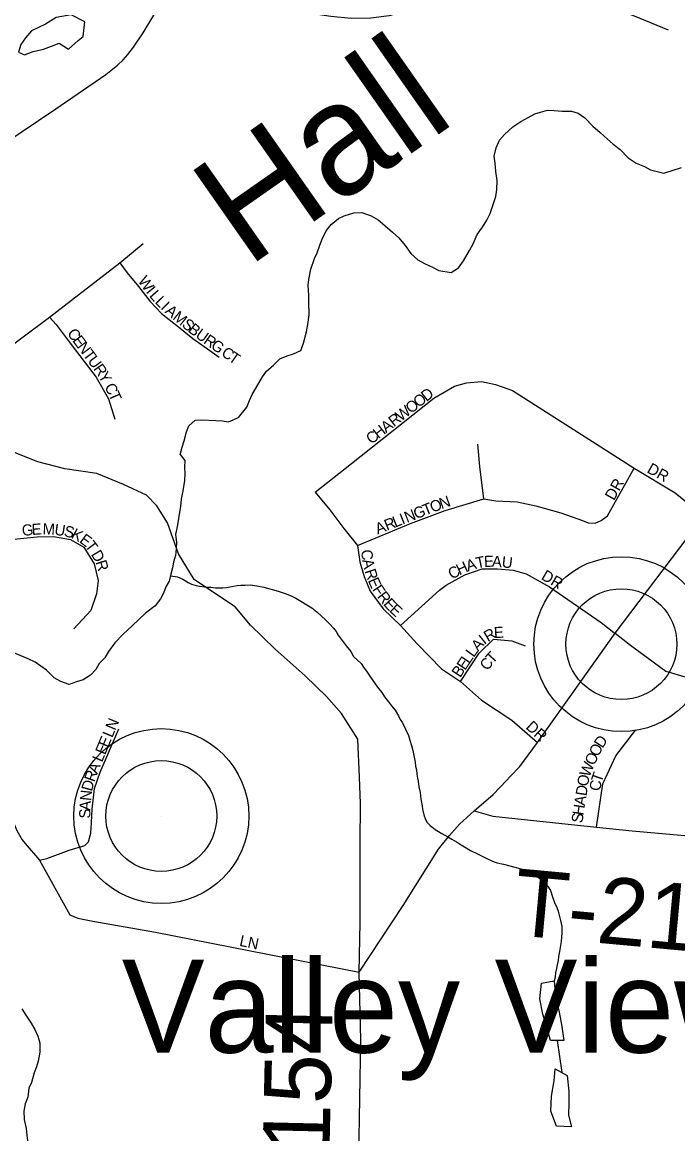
# Model space of a CAD drawing. Extents: x 1310247 to 1664935, y 235267 to 584339.
# Drawn here: x 1459518 to 1462461, y 411738 to 416732 of the extents above; entities that cross this region are included whole.
import ezdxf

# ---------------------------------------------------------------- set-up
doc = ezdxf.new("R2010")
doc.units = 0
for name, color, linetype in [('GM_X_County_Road', 7, 'Continuous'), ('GM_X_County_Road_Text', 7, 'Continuous'), ('GM_X_Minor_Lake', 7, 'Continuous'), ('GM_X_Minor_River', 7, 'Continuous'), ('GM_X_Minor_River_Text', 7, 'Continuous'), ('GM_X_Township_Road', 7, 'Continuous'), ('GM_X_Township_Road_Text', 7, 'Continuous'), ('GM_X_Township_Subdivision', 7, 'Continuous'), ('GM_X_Township_Subdivision_Text', 7, 'Continuous'), ('GM_X_Unincorporated', 7, 'Continuous'), ('GM_X_Unincorporated_Location', 7, 'Continuous'), ('GM_X_Unincorporated_Text', 7, 'Continuous')]:
    doc.layers.add(name, color=color, linetype=linetype)

msp = doc.modelspace()

# ---------------------------------------------------------------- linework, layer by layer
at = {"layer": 'GM_X_County_Road'}
for points in [[(1459435.1, 416186), (1459669, 416343.4), (1459893.6, 416496.7), (1459946.4, 416538.4), (1459972, 416563.5), (1459991.8, 416586.2), (1460017.8, 416619.2), (1460060.7, 416684.7), (1460147.8, 416827.3)], [(1461031.3, 412463.9), (1461031.3, 412463.9), (1461034.9, 412687.5), (1461034.9, 413042.4), (1461037.3, 413222.2), (1461032.5, 413340.5), (1461025.4, 413510.9), (1460952.1, 413626.8), (1460883.5, 413702.5), (1460787.9, 413795.4), (1460653.8, 413915.5), (1460542.5, 414023.4), (1460474.6, 414105.2), (1460376.7, 414169.9), (1460290.4, 414227.4), (1460219.8, 414342.9), (1460170, 414482.9), (1460123, 414559.5), (1460076, 414606.5), (1459973.3, 414655.2), (1459853.2, 414703.9), (1459708.7, 414724.8), (1459588.6, 414756.2), (1459433.7, 414818.8)], [(1461020.6, 411157.3), (1461021.3, 411185), (1461027.8, 411433.5), (1461029.8, 411633), (1461037.6, 412159.4), (1461031.3, 412463.9)]]:
    msp.add_lwpolyline(points, dxfattribs=at)
at = {"layer": 'GM_X_Minor_Lake'}
msp.add_line((1461919.9, 412156.8), (1461941.2, 412013.2), dxfattribs=at)
for points in [[(1459798.9, 416733.9), (1459737.2, 416765.3), (1459670.7, 416752.6), (1459622, 416723.5), (1459559.2, 416692.7), (1459532.4, 416661.2), (1459511.8, 416631.5), (1459501, 416597.6), (1459528.9, 416585), (1459567.3, 416600.2), (1459613.7, 416611.3), (1459650, 416624.6), (1459684.4, 416638), (1459726, 416611), (1459768.9, 416650.3), (1459791.4, 416667.8), (1459798.9, 416733.9)], [(1461906.6, 412425.7), (1461911.7, 412352.7), (1461928.4, 412284.1), (1461941.1, 412219.6), (1461949.9, 412157.2), (1461889.7, 412156.4), (1461876.7, 412206.9), (1461856, 412275.5), (1461841.4, 412344), (1461848.8, 412414.1)], [(1461911.3, 412029.5), (1461964.8, 412000.4), (1461971.4, 411928), (1461972.4, 411875.8), (1461971.3, 411821.6), (1461984.3, 411769.2), (1461916.2, 411772.5), (1461891.4, 411839.3), (1461894.8, 411907.4), (1461906.2, 411975.5)]]:
    msp.add_lwpolyline(points, dxfattribs=at)
at = {"layer": 'GM_X_Minor_River'}
for p, q in [((1461848.8, 412414.1), (1461906.6, 412425.7)), ((1461906.2, 411975.5), (1461911.3, 412029.5))]:
    msp.add_line(p, q, dxfattribs=at)
for points in [[(1460227.7, 414789.4), (1460236.3, 414823.3), (1460244.8, 414851.3), (1460255.6, 414891.2), (1460266.1, 414919.1), (1460294.6, 414944.7), (1460322.6, 414946.2), (1460386.7, 414943.1), (1460416.7, 414940.6), (1460444.6, 414936.1), (1460489, 414955.4), (1460525.9, 415002.9), (1460538.5, 415032.8), (1460550.9, 415058.7), (1460565.4, 415084.5), (1460596.4, 415138.1), (1460614.9, 415163.9), (1460645.5, 415191.5), (1460674, 415219.1), (1460708.3, 415232.5), (1460736.5, 415242.1), (1460768.8, 415257.6), (1460781.4, 415289.5), (1460794.4, 415341.4), (1460801, 415373.4), (1460805.8, 415417.4), (1460804.8, 415475.6), (1460805.4, 415505.7), (1460802.2, 415549.9), (1460804.6, 415576), (1460813.5, 415621.9), (1460830.4, 415669.8), (1460842.8, 415695.7), (1460853.4, 415725.6), (1460863.9, 415753.5), (1460882.7, 415795.3), (1460905.2, 415823), (1460937.8, 415850.5), (1460964, 415862.1), (1461006.3, 415875.4), (1461042.4, 415876.8), (1461084.1, 415862.1), (1461115.8, 415843.5), (1461145.4, 415818.9), (1461180.9, 415788.2), (1461208.5, 415763.6), (1461237.9, 415729), (1461263.3, 415692.5), (1461294.8, 415663.8), (1461324.5, 415647.3), (1461362.3, 415630.6), (1461388, 415616.1), (1461443.9, 415607.1), (1461476.4, 415628.6), (1461499, 415660.3), (1461525.8, 415706), (1461542.4, 415735.8), (1461561.2, 415777.6), (1461583.8, 415811.4), (1461604.4, 415843.1), (1461619, 415873), (1461631.7, 415912.9), (1461644.4, 415948.8), (1461649, 415980.8), (1461649.7, 416020.9), (1461644.4, 416061.1), (1461641.1, 416099.3), (1461637.6, 416129.4), (1461646.3, 416167.4), (1461661, 416201.3), (1461683.5, 416227), (1461720.2, 416262.4), (1461756.6, 416285.9), (1461789, 416303.4), (1461819.3, 416320.9), (1461845.5, 416328.5), (1461875.7, 416336), (1461905.7, 416335.5), (1461941.7, 416332.9), (1461983.7, 416332.1), (1462013.6, 416323.6), (1462043.3, 416303), (1462080.6, 416264.3), (1462112.1, 416235.7), (1462145.7, 416207), (1462171.3, 416184.5), (1462202.9, 416159.9), (1462238.2, 416123.1), (1462273.8, 416098.5), (1462311.6, 416083.8), (1462339.4, 416069.3), (1462399.2, 416054.2), (1462477.7, 416078.9)], [(1460227.7, 414789.4), (1460247.5, 414762.6), (1460246.7, 414732.5), (1460248, 414702.3), (1460247.2, 414672.2), (1460242.5, 414644.3), (1460237.8, 414618.3), (1460231, 414588.4), (1460228.2, 414556.3), (1460223.3, 414522.3), (1460218.5, 414492.3), (1460213.8, 414466.4), (1460206.9, 414430.4), (1460210, 414396.2), (1460209.3, 414366.1), (1460206.5, 414336.1), (1460197.7, 414306.2), (1460193, 414280.2), (1460184.2, 414246.3), (1460177.5, 414220.4), (1460162.8, 414194.7), (1460152.1, 414166.9), (1460139.4, 414141.1), (1460114.6, 414109.7), (1460071.7, 414076.7), (1460012.2, 414020), (1459971.3, 413982.9), (1459934.2, 413943.8), (1459905.2, 413904.4), (1459888.5, 413876.7), (1459863.8, 413851.3), (1459849.1, 413823.6), (1459824.4, 413798.1), (1459791.9, 413776.9), (1459761.6, 413767.6), (1459729.3, 413756.5), (1459691.6, 413769.5), (1459662, 413786.3), (1459626.9, 413821.4), (1459601.3, 413838.1), (1459575.8, 413856.8), (1459544.2, 413871.7), (1459472.9, 413901.7)], [(1460183.6, 414244.3), (1460214.7, 414240), (1460238.6, 414229.5), (1460262.4, 414215), (1460278.4, 414206.7), (1460298.3, 414200.4), (1460314.4, 414198.1), (1460336.4, 414195.7), (1460350.4, 414193.4), (1460364.5, 414193.2), (1460386.5, 414190.8), (1460418.6, 414190.2), (1460434.7, 414191.9), (1460450.8, 414195.7), (1460466.9, 414197.4), (1460483, 414201.1), (1460499.1, 414202.9), (1460519.2, 414202.5), (1460541.3, 414204.1), (1460571.3, 414199.6), (1460603.3, 414193), (1460667.3, 414175.8), (1460699.2, 414165.2), (1460725.1, 414154.7), (1460747, 414144.3), (1460818.6, 414100.9), (1460840.3, 414082.4), (1460862.1, 414063.9), (1460879.9, 414047.6), (1460897.6, 414029.2), (1460915.4, 414008.8), (1460927.2, 413994.5), (1460936.9, 413978.3), (1460972.2, 413929.5), (1460993.9, 413905), (1461005.6, 413882.7), (1461039.2, 413850), (1461050.9, 413833.7), (1461066.6, 413811.3), (1461082.3, 413789), (1461099.9, 413764.5), (1461113.6, 413744.2), (1461133.3, 413719.8), (1461145, 413701.5), (1461162.7, 413679.1), (1461176.5, 413660.8), (1461192.2, 413640.4), (1461207.8, 413616), (1461215.6, 413599.8), (1461225.4, 413583.6), (1461252.5, 413526.9), (1461258.2, 413506.7), (1461265.8, 413482.5), (1461271.4, 413460.3), (1461282.6, 413407.9), (1461284.3, 413389.8), (1461288.1, 413373.6), (1461289.7, 413353.5), (1461293.4, 413335.4), (1461295.2, 413321.3), (1461298.8, 413297.1), (1461304.4, 413270.9), (1461307.9, 413240.7), (1461313.4, 413210.5), (1461315.2, 413196.4), (1461320.7, 413170.2), (1461328.4, 413150), (1461336.2, 413135.8), (1461350.1, 413123.5), (1461371.8, 413105), (1461401.6, 413086.4), (1461429.5, 413071.9), (1461447.4, 413061.5), (1461467.3, 413049.1), (1461481.2, 413040.9), (1461503, 413026.4), (1461530.8, 413009.9), (1461562.7, 412995.2), (1461612.5, 412970.3), (1461636.4, 412959.8), (1461650.3, 412955.5), (1461678.3, 412949), (1461730.3, 412936.1), (1461752.3, 412929.7), (1461776.2, 412921.2), (1461796.2, 412914.8), (1461810.1, 412908.6), (1461826, 412898.2), (1461843.8, 412883.9), (1461857.7, 412871.6), (1461879.4, 412847.1), (1461889.1, 412830.9), (1461898.7, 412802.6), (1461908.3, 412776.3), (1461917.9, 412754), (1461923.7, 412737.9), (1461929.4, 412719.7), (1461935, 412695.5), (1461940.6, 412669.3), (1461940.1, 412641.2), (1461937.4, 412601.1)], [(1461937.4, 412601.1), (1461930.7, 412557), (1461926.3, 412535), (1461924, 412517), (1461919.6, 412496.9), (1461917.3, 412480.9), (1461913, 412462.9), (1461910.6, 412440.9), (1461906.6, 412425.7)], [(1459515.6, 412298.7), (1459534.9, 412270.1), (1459558, 412235.4)], [(1459558, 412235.4), (1459575.2, 412206.8), (1459588.5, 412176.3), (1459597.7, 412146), (1459596.6, 412103.9), (1459589.6, 412063.9), (1459582.9, 412038), (1459572.2, 412012.2), (1459559.1, 411968.3), (1459548.4, 411942.5), (1459543.4, 411902.5), (1459530.6, 411872.7), (1459525.7, 411838.8), (1459526.8, 411802.6), (1459535.7, 411762.2), (1459539, 411732), (1459542.3, 411705.8), (1459550, 411615.3), (1459549.1, 411583.2), (1459543.9, 411537.2), (1459535, 411501.3), (1459508.6, 411483.9)]]:
    msp.add_lwpolyline(points, dxfattribs=at)
at = {"layer": 'GM_X_Township_Road'}
for points in [[(1461709.2, 413343), (1461751.7, 413388.6), (1461831.5, 413495.8), (1462180.1, 413986.4), (1462578.2, 414511.9), (1462719.1, 414714.3), (1462786.1, 414816.9), (1462842.6, 414921.5), (1462941, 415057.6), (1463154.6, 415338.1), (1463275.8, 415509.9), (1463559.9, 415879.2), (1463677.1, 416025.3), (1463801.6, 416137.1), (1463964.5, 416275.5)], [(1461031.3, 412463.9), (1461228.3, 412763.1), (1461387.4, 413016.1), (1461435.7, 413078.5), (1461480.8, 413129.6), (1461547, 413189), (1461632.3, 413262.6), (1461693, 413325.6), (1461709.2, 413343)], [(1461547, 413189), (1461630.5, 413164.2), (1462096.7, 413115.2), (1462257, 413099.3), (1462998.8, 413032.9), (1463165.7, 413010), (1463347.6, 412994.4), (1463631.5, 412978), (1463802.1, 412959.9), (1463959, 412938.7), (1463967.3, 412938.5)]]:
    msp.add_lwpolyline(points, dxfattribs=at)
at = {"layer": 'GM_X_Township_Subdivision'}
for points in [[(1460221.5, 416946.3), (1460260.2, 416923.1), (1460287.3, 416914), (1460374.2, 416898.9), (1460427.5, 416865.7), (1460475.1, 416844.7), (1460544.6, 416819.2), (1460618.2, 416803.7), (1460743.8, 416783.1), (1460903.3, 416759.8), (1460995.1, 416750), (1461083.2, 416752.2), (1461165.4, 416762.6), (1461314.2, 416799.8), (1461429.1, 416843.6), (1461535.8, 416875.6), (1461643.8, 416877.4), (1461773.7, 416872.8), (1461939.4, 416855.4), (1462140.4, 416807.3), (1462265.4, 416760.6), (1462418.1, 416697.3)], [(1458714.9, 413661.4), (1458894.2, 414098.2), (1458989.9, 414319.3), (1459064.8, 414495.1), (1459089.1, 414559.5), (1459114.4, 414607), (1459120, 414669), (1459116.2, 414718.1), (1459113.3, 414778.8), (1459122, 414830.9), (1459163, 414931.6), (1459190.4, 415001.4), (1459233.8, 415089.1), (1459278.1, 415137.3), (1459640.5, 415406.2), (1459956.5, 415650.9), (1460060.6, 415737.7)], [(1459956.5, 415650.9), (1459989.9, 415605.6), (1460039.7, 415545), (1460092.4, 415476.7), (1460144.1, 415423.9), (1460219.3, 415363.4), (1460284.7, 415310.7), (1460350.2, 415264.8), (1460402.9, 415227.7)], [(1459640.5, 415406.2), (1459670.3, 415373.4), (1459733.9, 415290.5), (1459800.4, 415201.9), (1459850.5, 415137.3), (1459905.4, 415040), (1459934.4, 414948.4)], [(1460832.8, 414620.1), (1460996.1, 414749.9), (1461366.7, 415043), (1461458.8, 415097.4), (1461513.2, 415112), (1461580.2, 415118.3), (1461643, 415103.7), (1461718.5, 415077.2), (1462062.4, 414858.8), (1462264.8, 414728.9), (1462449, 414618), (1462578.2, 414511.9)], [(1461590.7, 414590.7), (1461571.8, 414735.2), (1461563.5, 414835.7)], [(1461023.9, 414380.2), (1461262, 414479.8), (1461416.9, 414538.4), (1461590.7, 414590.7), (1461644.4, 414581), (1461740.2, 414577.7), (1461823.5, 414558.9), (1461936.3, 414527), (1462033, 414493.6), (1462058.6, 414482.7), (1462090.6, 414481.7), (1462116.9, 414492.8), (1462145.6, 414513.9), (1462264.8, 414728.9)], [(1460832.8, 414620.1), (1460899.8, 414540.5), (1460962.6, 414456.7), (1461023.9, 414380.2), (1461033.8, 414308.1), (1461052.7, 414241.1), (1461079.9, 414176.2), (1461138.5, 414096.7), (1461215.9, 414021.3), (1461291.3, 413939.7), (1461400.2, 413826.6), (1461486, 413770.1), (1461580.2, 413686.3), (1461716.3, 413596.3), (1461831.5, 413495.8)], [(1459064.8, 414495.1), (1459200, 414438.7), (1459296.2, 414406.3), (1459371.1, 414397.6), (1459451.1, 414406.3), (1459585.2, 414420.2), (1459658.3, 414422), (1459734.8, 414408.1), (1459794, 414373.3), (1459840.5, 414298.7), (1459858.4, 414223.5), (1459851.5, 414164.4), (1459825.4, 414089.5), (1459750.5, 414006)], [(1461215.9, 414021.3), (1461390.9, 414180.2), (1461421.7, 414203.2), (1461504.9, 414249.5), (1461582.3, 414276.7), (1461651.9, 414275.7), (1461721.7, 414269.4), (1461781, 414253.3), (1461884.9, 414195.7), (1462117.2, 414035.3), (1462174.7, 413990.7)], [(1461486, 413770.1), (1461569.7, 413897.8), (1461634.6, 413960.6), (1461716.3, 413952.2), (1461776.4, 413930.7)], [(1462174.7, 413990.7), (1462180.1, 413986.4), (1462249.5, 413932.5), (1462407.4, 413816.9), (1462499.1, 413788.6), (1462615.6, 413782.1), (1462756.5, 413785.3)], [(1459595.1, 412967.8), (1459628.2, 412975), (1459728.8, 413011.6), (1459799.3, 413032.4), (1459815.7, 413050.2), (1459826.4, 413088.2), (1459829.2, 413136.3), (1459832.3, 413196.5), (1459842.4, 413288.4), (1459868.4, 413361.8), (1459951.2, 413557)], [(1462096.7, 413115.2), (1462125, 413309.4), (1462182.4, 413435.8), (1462272.7, 413552.3)], [(1459356.1, 413540.4), (1459397.1, 413425.3), (1459421.7, 413358.4), (1459457.9, 413184.3), (1459494.6, 413100.4), (1459518.2, 413057.8), (1459531.9, 413041.7)], [(1459531.9, 413041.7), (1459595.1, 412967.8), (1459731.2, 412721.8), (1459767.8, 412706.4), (1459835.3, 412693.4), (1460116.8, 412643.7), (1461031.3, 412463.9)]]:
    msp.add_lwpolyline(points, dxfattribs=at)
at = {"layer": 'GM_X_Unincorporated'}
for centre, radius in [((1462208, 413937.5), 392.8), ((1462208, 413937.5), 249), ((1460142.6, 413165.4), 392.8), ((1460142.6, 413165.4), 249)]:
    msp.add_circle(centre, radius, dxfattribs=at)
at = {"layer": 'GM_X_Unincorporated_Location'}
for p, q in [((1462208, 413937.5), (1462208, 413937.5)), ((1460142.6, 413165.4), (1460142.6, 413165.4))]:
    msp.add_line(p, q, dxfattribs=at)

# ---------------------------------------------------------------- texts
at = {"layer": 'GM_X_County_Road_Text'}
msp.add_text('C-154', height=300, rotation=88.7197, dxfattribs=at).set_placement((1460887.8, 411223.3))
at = {"layer": 'GM_X_Minor_River_Text'}
msp.add_text('Hall', height=500.04, rotation=35.0042, dxfattribs=at).set_placement((1460529.1, 415626.4))
at = {"layer": 'GM_X_Township_Road_Text'}
msp.add_text('T-211', height=300, rotation=354.7305, dxfattribs=at).set_placement((1461714.2, 412631.6))
at = {"layer": 'GM_X_Township_Subdivision_Text'}
for s, rotation, p in [('W', 305.5181, (1460035.3, 415569.4)), ('I', 309.2984, (1460070.7, 415519.9)), ('L', 311.216, (1460085.9, 415501.5)), ('L', 314.8347, (1460111.4, 415472.5)), ('I', 316.2135, (1460137.2, 415446.7)), ('A', 320.2383, (1460155.9, 415428.9)), ('M', 320.9731, (1460190.3, 415400.3)), ('S', 320.922, (1460231.3, 415367.1)), ('C', 306.6076, (1459717.4, 415333.4)), ('B', 321.5273, (1460259, 415344.5)), ('U', 324.4482, (1460292.3, 415318.2)), ('E', 306.6217, (1459741, 415301.6)), ('N', 306.6103, (1459762, 415273.4)), ('R', 325.1638, (1460328.6, 415292.2)), ('G', 325.1763, (1460361.1, 415269.6)), ('T', 306.6217, (1459788.3, 415238)), ('C', 325.1651, (1460408.1, 415236.9)), ('T', 325.1851, (1460440.6, 415214.3)), ('U', 306.6103, (1459809.3, 415209.8)), ('R', 305.3203, (1459835.3, 415174.7)), ('Y', 299.9591, (1459857.5, 415143.5)), ('C', 298.3468, (1459885.6, 415094.1)), ('T', 293.7655, (1459904, 415060.2)), ('O', 37.8427, (1461297.6, 414998.3)), ('D', 37.3114, (1461332.3, 415025.2)), ('W', 37.8484, (1461217.7, 414936.2)), ('O', 37.8269, (1461262.8, 414971.2)), ('R', 37.8565, (1461186.4, 414911.9)), ('H', 37.8427, (1461116.9, 414857.9)), ('A', 37.8427, (1461151.7, 414884.9)), ('C', 37.8366, (1461085.7, 414833.6)), ('DR', 330.6435, (1462319.3, 414711.2)), ('DR', 60.639, (1462174.5, 414580)), ('N', 19.4994, (1461400.3, 414543.5)), ('G', 21.6431, (1461286.2, 414498.3)), ('T', 21.6527, (1461327.1, 414514.5)), ('O', 21.5741, (1461359.8, 414527.5)), ('R', 21.6391, (1461155.3, 414446.4)), ('L', 21.6527, (1461192.1, 414461)), ('I', 21.6309, (1461224.8, 414474)), ('N', 21.6443, (1461245.3, 414482.1)), ('G', 5.6072, (1459518.7, 414423.6)), ('E', 4.0739, (1459562.1, 414427.8)), ('M', 358.6339, (1459609.2, 414430.6)), ('U', 351.4433, (1459660.3, 414429.4)), ('S', 347.2756, (1459702.9, 414423.1)), ('K', 332.7311, (1459734.1, 414416.5)), ('A', 21.6431, (1461114.4, 414430.1)), ('E', 323.6492, (1459771.4, 414397.4)), ('T', 306.9956, (1459797, 414379.2)), ('D', 300.5176, (1459825, 414341.6)), ('C', 275.887, (1461039.3, 414360.3)), ('R', 287.667, (1459846.1, 414306.4)), ('A', 282.049, (1461044.2, 414315.1)), ('H', 24.8057, (1461480.7, 414246.3)), ('A', 17.5848, (1461519.1, 414264.2)), ('T', 11.7226, (1461559.7, 414277.1)), ('E', 2.2404, (1461592, 414284)), ('A', 356.7632, (1461625.9, 414285.4)), ('U', 353.6719, (1461669.2, 414283)), ('R', 288.1001, (1461054.9, 414266.5)), ('C', 29.9557, (1461447.5, 414227.1)), ('DR', 329.535, (1461844.4, 414231.4)), ('E', 293.5605, (1461069.1, 414224)), ('F', 303.4961, (1461087.7, 414183.5)), ('R', 307.6357, (1461109.4, 414150.9)), ('E', 312.3951, (1461136.5, 414116.1)), ('E', 317.0164, (1461163.3, 414086.9)), ('R', 30.4015, (1461608.7, 413946.1)), ('E', 3.4996, (1461636.9, 413964.3)), ('A', 46.8705, (1461564.5, 413902.5)), ('I', 39.0217, (1461593.2, 413933.3)), ('L', 54.1956, (1461544.9, 413875.2)), ('T', 47.7447, (1461630.4, 413846.3)), ('E', 56.1811, (1461506, 413817.1)), ('L', 56.1995, (1461525.6, 413846.3)), ('C', 54.1405, (1461608.1, 413815.3)), ('B', 56.2156, (1461484, 413784.2)), ('N', 67.3179, (1459935.8, 413546.9)), ('DR', 317.1199, (1461775.5, 413561.5)), ('E', 67.3108, (1459903.5, 413469.8)), ('L', 67.3151, (1459922.2, 413514.4)), ('D', 57.0678, (1462123.1, 413467)), ('E', 67.2982, (1459890, 413437.3)), ('O', 64.0311, (1462104.6, 413428.8)), ('L', 67.3108, (1459876.4, 413404.8)), ('W', 67.6866, (1462064, 413337.1)), ('O', 64.0311, (1462085.3, 413389.3)), ('R', 70.1518, (1459841.7, 413315.2)), ('A', 68.162, (1459855, 413352)), ('T', 70.9949, (1462118.2, 413312.6)), ('D', 75.3065, (1459830.9, 413273.7)), ('D', 81.1558, (1462051.3, 413253.1)), ('O', 81.1714, (1462058.1, 413296.6)), ('C', 82.6701, (1462113.8, 413275.9)), ('N', 84.2415, (1459826.9, 413232)), ('A', 81.1938, (1462044.5, 413209.7)), ('A', 86.1946, (1459824, 413188.5)), ('H', 81.1558, (1462037.8, 413166.2)), ('S', 89.3989, (1459823.7, 413154.1)), ('S', 81.1666, (1462032.4, 413131.4)), ('LN', 348.1073, (1460490.6, 412582.6))]:
    msp.add_text(s, height=50, rotation=rotation, dxfattribs=at).set_placement(p)
at = {"layer": 'GM_X_Unincorporated_Text'}
msp.add_text('Valley View Heights', height=417, rotation=0, dxfattribs=at).set_placement((1459965.1, 412102.4))

doc.saveas('drawing.dxf')
